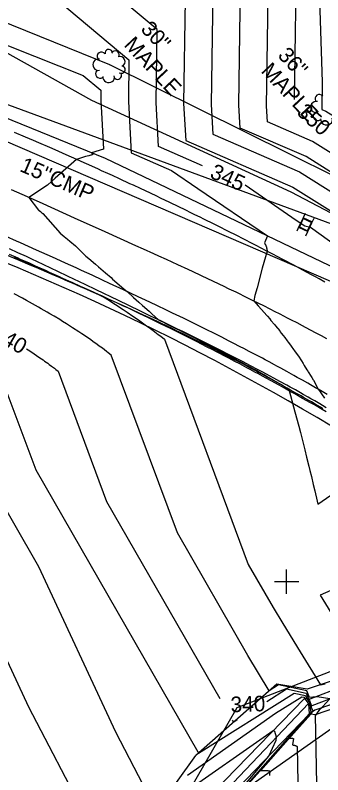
# Model space of a CAD drawing. Extents: x 487096 to 489566, y 221939 to 224454.
# Drawn here: x 488276.8 to 488339.9, y 223512.7 to 223668.7 of the extents above; entities that cross this region are included whole.
import ezdxf

# ---------------------------------------------------------------- set-up
doc = ezdxf.new("R2010")
doc.units = 0
for name, color, linetype in [('SV_BKLN_BKLN', 7, 'Continuous'), ('SV_BKLN_EARTH_TOP', 7, 'Continuous'), ('SV_GDRL_GR', 7, 'Continuous'), ('SV_PIPE_CM_15', 7, 'Continuous'), ('SV_PIPE_CM_TX', 7, 'Continuous'), ('SV_ROAD_BITRD', 7, 'Continuous'), ('SV_ROWL_HWYLOC', 7, 'Continuous'), ('SV_SIGN_SIGN', 7, 'Continuous'), ('SV_SURF_INDEX_CONTOUR', 7, 'Continuous'), ('SV_SURF_INTER_CONTOUR', 7, 'Continuous'), ('SV_SURF_SPOT', 7, 'Continuous'), ('SV_TRAF_PVMTL', 7, 'Continuous'), ('SV_TREE_TREELN', 7, 'Continuous'), ('SV_TREE_TREEVEG', 7, 'Continuous'), ('SV_TREE_TREEVEG_TX', 7, 'Continuous'), ('SV_UTOH_OVERHEAD_LINES', 7, 'Continuous'), ('SV_WATR_INWETF', 7, 'Continuous'), ('SV_WATR_STREAM', 7, 'Continuous')]:
    doc.layers.add(name, color=color, linetype=linetype)

msp = doc.modelspace()

# ---------------------------------------------------------------- linework, layer by layer
at = {"layer": 'SV_BKLN_BKLN'}
for points in [[(488339.95, 223587.83), (488339.42, 223588.15), (488338.36, 223588.77), (488337.57, 223589.24), (488337.04, 223589.54), (488335.98, 223590.16), (488335.45, 223590.47), (488334.38, 223591.07), (488333.32, 223591.68), (488332.61, 223592.08), (488331.18, 223592.88), (488329.97, 223593.55), (488329.16, 223593.99), (488328.62, 223594.28), (488327.55, 223594.87), (488326.73, 223595.31), (488326.19, 223595.6), (488325.11, 223596.17), (488323.48, 223597.03), (488322.39, 223597.6), (488321.67, 223597.98), (488320.21, 223598.73), (488319.39, 223599.15), (488317.75, 223599.99), (488316.1, 223600.82), (488315, 223601.36), (488314.27, 223601.73), (488312.8, 223602.45), (488311.14, 223603.26), (488310.04, 223603.8), (488309.3, 223604.15), (488307.82, 223604.86), (488306.71, 223605.39), (488305.97, 223605.74), (488304.48, 223606.43), (488303.74, 223606.78), (488302.26, 223607.47), (488300.77, 223608.16), (488299.78, 223608.61), (488297.79, 223609.52), (488295.94, 223610.35), (488294.7, 223610.9), (488293.88, 223611.27), (488292.23, 223612), (488291, 223612.55), (488290.17, 223612.91), (488288.52, 223613.63), (488287.69, 223613.99), (488286.04, 223614.7), (488284.39, 223615.42), (488283.28, 223615.89), (488281.07, 223616.83), (488279.83, 223617.36), (488277.34, 223618.4), (488274.85, 223619.44)], [(488394.74, 223534.86), (488364.7, 223537.11), (488337.65, 223526.86), (488337, 223527.31)], [(488337, 223527.31), (488308.63, 223497.45)]]:
    msp.add_lwpolyline(points, dxfattribs=at)
at = {"layer": 'SV_BKLN_EARTH_TOP'}
for points in [[(488393.96, 223536.98), (488391.41, 223542.53), (488364.31, 223539.49), (488336.74, 223530.25), (488330.51, 223531.3), (488313.83, 223516.63)], [(488395.58, 223534.31), (488365.44, 223534.31), (488338.38, 223524.96), (488337.45, 223525.1)], [(488337.45, 223525.1), (488314.81, 223499.82)], [(488301.95, 223500.02), (488313.83, 223516.63)]]:
    msp.add_lwpolyline(points, dxfattribs=at)
at = {"layer": 'SV_GDRL_GR'}
msp.add_lwpolyline([(488340.6, 223587.23), (488339.8, 223587.69), (488338.2, 223588.61), (488337.39, 223589.07), (488335.79, 223589.97), (488334.18, 223590.88), (488333.11, 223591.48), (488332.39, 223591.87), (488331.44, 223592.4), (488330.96, 223592.67), (488329.34, 223593.55), (488328.27, 223594.14), (488327.55, 223594.53), (488326.59, 223595.05), (488326.11, 223595.31), (488325.03, 223595.89), (488324.31, 223596.27), (488323.34, 223596.79), (488322.86, 223597.04), (488321.9, 223597.55), (488320.61, 223598.23), (488319.97, 223598.56), (488318.52, 223599.32), (488317.07, 223600.07), (488316.34, 223600.44), (488314.89, 223601.18), (488314.16, 223601.55), (488313.07, 223602.11), (488311.43, 223602.93), (488309.78, 223603.75), (488308.96, 223604.16), (488307.5, 223604.88), (488306.76, 223605.24), (488305.66, 223605.77), (488304.01, 223606.57), (488302.35, 223607.36), (488301.53, 223607.76), (488299.87, 223608.54), (488299.03, 223608.93), (488297.79, 223609.52), (488295.95, 223610.36), (488294.73, 223610.93), (488293.91, 223611.3), (488292.27, 223612.04), (488291.04, 223612.6), (488290.22, 223612.97), (488288.58, 223613.7), (488287.76, 223614.06), (488286.11, 223614.79), (488284.47, 223615.51), (488283.37, 223615.98), (488282.63, 223616.3), (488281.16, 223616.93), (488279.92, 223617.46), (488279.09, 223617.82), (488277.44, 223618.52), (488276.61, 223618.87)], dxfattribs=at)
at = {"layer": 'SV_PIPE_CM_15'}
msp.add_lwpolyline([(488383.93, 223595.7), (488200.04, 223675.13)], dxfattribs=at)
at = {"layer": 'SV_ROAD_BITRD'}
for points in [[(488436.8, 223529.84), (488436.16, 223531.3), (488435.52, 223532.76), (488434.87, 223534.21), (488434.21, 223535.66), (488433.55, 223537.11), (488433.5, 223537.21), (488438.04, 223566.2), (488412.1, 223588.33), (488389.51, 223592.95), (488385.2, 223591.02), (488344.38, 223615.78), (488295.35, 223639.2), (488243.64, 223660.28)], [(488340.64, 223588.06), (488339.85, 223588.52), (488339.32, 223588.83), (488338.27, 223589.44), (488337.48, 223589.89), (488336.95, 223590.19), (488335.9, 223590.79), (488335.37, 223591.09), (488334.31, 223591.69), (488333.24, 223592.28), (488332.53, 223592.67), (488331.11, 223593.45), (488329.9, 223594.1), (488329.1, 223594.53), (488327.49, 223595.39), (488326.68, 223595.82), (488325.06, 223596.66), (488323.44, 223597.51), (488322.35, 223598.07), (488321.63, 223598.44), (488320.18, 223599.17), (488319.37, 223599.59), (488317.73, 223600.41), (488316.1, 223601.23), (488315, 223601.77), (488312.82, 223602.86), (488311.17, 223603.67), (488310.08, 223604.2), (488307.88, 223605.27), (488306.78, 223605.81), (488304.59, 223606.87), (488302.39, 223607.93), (488297.99, 223610.05), (488293.41, 223612.26), (488291.12, 223613.36), (488287.68, 223615.01), (488285.39, 223616.1), (488284.24, 223616.65), (488282.52, 223617.46), (488280.22, 223618.55), (488279.07, 223619.09), (488277.35, 223619.89), (488275.62, 223620.69)]]:
    msp.add_lwpolyline(points, dxfattribs=at)
at = {"layer": 'SV_ROWL_HWYLOC'}
msp.add_lwpolyline([(487756.92, 223854.03), (487819.74, 223823.93), (487982.51, 223759.36), (488009.69, 223754.74), (488041.14, 223750.63), (488071.96, 223735.45), (488100.92, 223722.74), (488124.66, 223715.6), (488155.68, 223709.25), (488178.9, 223706.07), (488296.16, 223658.56), (488379.4, 223617.17), (488410.15, 223595.68), (488443.8, 223549.21), (488472.24, 223469.86), (488477.06, 223418.16), (488475.62, 223352.08), (488474.08, 223317.48), (488463.17, 223231.25), (488461.58, 223189.46)], dxfattribs=at)
msp.add_arc((488082.83, 223151.77), 504.05, 56.3623, 68.8615, dxfattribs=at)
at = {"layer": 'SV_SIGN_SIGN'}
for p, q in [((488336.27, 223627.93), (488335.86, 223627.05)), ((488337.7, 223626.04), (488338.13, 223626.98)), ((488335.01, 223625.26), (488334.57, 223624.34)), ((488336.46, 223623.37), (488336.87, 223624.25))]:
    msp.add_line(p, q, dxfattribs=at)
for points in [[(488335.87, 223627.06), (488335.02, 223625.25), (488336.8, 223624.41), (488337.65, 223626.22)], [(488336.85, 223624.24), (488337.7, 223626.05), (488335.91, 223626.88), (488335.07, 223625.06)]]:
    msp.add_lwpolyline(points, close=True, dxfattribs=at)
at = {"layer": 'SV_SURF_INDEX_CONTOUR'}
for points in [[(488315.25, 223637.73), (488306.19, 223641.67), (488305.69, 223650.74), (488305.9, 223665.72), (488280.6, 223686.87), (488279.19, 223687.43), (488278.94, 223688.82), (488279.46, 223690.16), (488279.91, 223705.25)], [(488334.21, 223693.47), (488334.54, 223683.57), (488334.08, 223651.34)], [(488346.42, 223618.58), (488337.38, 223625.05), (488336.21, 223625.31), (488334.48, 223626.49), (488323.99, 223633.76)], [(488279.07, 223600.15), (488279.76, 223599.71), (488280.71, 223599.09), (488281.17, 223598.78), (488281.84, 223598.32), (488282.51, 223597.86), (488282.83, 223597.63), (488283.47, 223597.17), (488283.78, 223596.94), (488284.25, 223596.6), (488284.85, 223596.15), (488285.15, 223595.92), (488285.58, 223595.58), (488295.54, 223568.82), (488318.79, 223528.32)], [(488328.41, 223527.75), (488332.45, 223530.29), (488336.48, 223529.45), (488336.98, 223528.22), (488337.21, 223527.93), (488337.51, 223526.96), (488337.55, 223526.47), (488337.97, 223525.72), (488337.39, 223525.12), (488333.04, 223520.17), (488333.06, 223520.17), (488333.15, 223520.17), (488333.23, 223520.17), (488333.32, 223520.17), (488333.4, 223520.17), (488333.47, 223520.17), (488333.55, 223520.17), (488333.62, 223520.16), (488333.69, 223520.16), (488333.75, 223520.15), (488333.82, 223520.15), (488333.88, 223520.14), (488333.72, 223518.8), (488333.79, 223518.79), (488333.86, 223518.78), (488333.93, 223518.77), (488333.99, 223518.75), (488334.06, 223518.74), (488334.11, 223518.72), (488334.17, 223518.71), (488334.23, 223518.7), (488334.28, 223518.68), (488334.33, 223518.67), (488334.38, 223518.65), (488334.42, 223518.64), (488334.46, 223518.62), (488334.5, 223518.6), (488334.53, 223518.57), (488334.56, 223518.55), (488334.59, 223518.53), (488334.62, 223518.51), (488334.65, 223518.48), (488335.11, 223492.49)], [(488322.34, 223523.94), (488321.65, 223523.5), (488321.41, 223523.91)]]:
    msp.add_lwpolyline(points, dxfattribs=at)
at = {"layer": 'SV_SURF_INTER_CONTOUR'}
for points in [[(488344.4, 223638.61), (488337.84, 223642.72), (488328.56, 223646.76), (488328.39, 223649.96), (488328.96, 223690.61)], [(488338.62, 223690.85), (488339.81, 223654.94), (488339.74, 223649.58), (488339.75, 223649.3), (488340.55, 223648.95), (488341.11, 223648.6), (488357.67, 223638.69), (488363.82, 223635.84), (488384.77, 223627.51), (488386.19, 223626.24), (488404.97, 223613.69), (488414.47, 223607.86), (488430.46, 223603.61), (488430.99, 223603.65), (488432.06, 223604.18), (488443, 223609.09)], [(488346.04, 223633.62), (488336.49, 223639.61), (488322.97, 223645.48), (488322.71, 223650.16), (488323.2, 223684.39)], [(488317.43, 223678.16), (488317.04, 223650.35), (488317.37, 223644.21), (488335.13, 223636.49), (488347.68, 223628.62)], [(488285.67, 223671.59), (488300.14, 223659.5), (488300.02, 223650.93), (488300.59, 223640.39), (488308.89, 223636.78), (488314.27, 223633.05), (488328.54, 223623.34), (488327.95, 223621.89), (488328.01, 223621.78), (488328.11, 223621.6), (488328.14, 223621.54), (488328.2, 223621.4), (488328.25, 223621.29), (488328.28, 223621.21), (488328.34, 223621.05), (488328.38, 223620.91), (488328.44, 223620.69), (488328.53, 223620.22), (488328.53, 223620.17), (488327.47, 223616.69), (488326.45, 223612.7), (488326, 223611.13), (488325.74, 223609.98), (488326.66, 223608.99), (488326.72, 223608.92), (488327.3, 223608.28), (488327.35, 223608.22), (488328.42, 223607.02), (488328.54, 223606.86), (488329.04, 223606.29), (488329.29, 223605.97), (488330, 223605.14), (488330.21, 223604.86), (488331.07, 223603.83), (488331.19, 223603.66), (488331.4, 223603.37), (488331.79, 223602.89), (488332.1, 223602.45), (488332.64, 223601.78), (488332.81, 223601.53), (488333.28, 223600.93), (488333.56, 223600.52), (488333.77, 223600.24), (488334.24, 223599.53), (488334.92, 223598.61), (488335.54, 223597.65), (488335.88, 223597.1), (488336.13, 223596.75), (488336.68, 223595.84), (488336.87, 223595.57), (488336.95, 223595.44), (488337.53, 223594.45), (488337.65, 223594.28), (488337.95, 223593.75), (488337.99, 223593.68), (488338.63, 223592.54), (488338.65, 223592.5), (488338.99, 223591.88), (488338.99, 223591.88), (488339.03, 223591.79), (488339.54, 223591.08), (488339.67, 223590.88), (488340.26, 223590.03)], [(488311.67, 223671.94), (488311.36, 223650.54), (488311.78, 223642.94), (488333.78, 223633.37), (488349.32, 223623.63)], [(488265.33, 223666.37), (488290.74, 223656.31), (488294.37, 223653.27), (488294.34, 223651.12), (488294.89, 223641.12), (488292.47, 223640.37), (488292.73, 223640.05), (488292.73, 223640.04), (488292.71, 223640.04), (488292.7, 223640.03), (488292.67, 223640.02), (488292.63, 223640), (488292.59, 223639.99), (488292.5, 223639.97), (488292.4, 223639.94), (488292.31, 223639.92), (488292.07, 223639.85), (488291.88, 223639.8), (488291.22, 223639.61), (488289.37, 223639.05), (488284.99, 223635.2), (488283.38, 223633.78), (488279.59, 223631.2), (488281.6, 223628.62), (488281.72, 223628.53), (488281.97, 223628.32), (488282.25, 223628.09), (488282.45, 223627.92), (488286, 223623.89), (488286.83, 223623.24), (488287.52, 223622.68), (488288.02, 223622.26), (488289.14, 223621.32), (488291.26, 223619.2), (488291.88, 223618.69), (488293.25, 223617.56), (488293.88, 223616.96), (488295.35, 223615.72), (488296.45, 223614.79), (488296.78, 223614.48), (488299.1, 223612.47), (488299.18, 223612.41), (488299.75, 223611.9), (488301.09, 223610.66), (488302.15, 223609.74), (488302.94, 223609.02), (488304.26, 223607.85), (488304.83, 223607.33), (488306.21, 223606.08), (488306.77, 223605.8), (488306.78, 223605.8), (488307.83, 223605.28), (488307.88, 223605.26), (488307.94, 223605.22), (488310, 223604.2), (488310.07, 223604.16), (488311.03, 223603.68), (488311.17, 223603.61), (488312.54, 223602.92), (488312.81, 223602.79), (488313.09, 223602.65), (488314.83, 223601.76), (488315, 223601.67), (488315.8, 223601.27), (488316.1, 223601.11), (488317.22, 223600.54), (488317.74, 223600.27), (488318.77, 223599.74), (488319.38, 223599.42), (488319.86, 223599.17), (488320.2, 223598.99), (488320.99, 223598.57), (488321.65, 223598.22), (488322.01, 223598.02), (488322.37, 223597.83), (488322.88, 223597.56), (488323.46, 223597.24), (488324.14, 223596.88), (488325.09, 223596.36), (488325.81, 223595.96), (488326.35, 223595.67), (488326.72, 223595.46), (488326.96, 223595.33), (488327.53, 223595.01), (488327.93, 223594.79), (488328.72, 223594.34), (488329.15, 223594.09), (488329.3, 223594.01), (488329.96, 223593.63), (488330.13, 223593.53), (488331.17, 223592.93), (488331.29, 223592.86), (488332.6, 223592.09), (488332.62, 223592.08), (488332.94, 223591.89), (488333.3, 223590.59), (488334.2, 223587.21), (488334.97, 223584.28), (488335.32, 223582.95), (488335.94, 223580.53), (488336.22, 223579.43), (488336.61, 223577.89), (488337.08, 223576.02), (488337.29, 223575.16), (488337.58, 223573.95), (488337.98, 223572.3), (488338.29, 223570.97), (488338.43, 223570.35), (488338.63, 223569.47), (488338.91, 223568.25), (488348.2, 223574.66)], [(488275.57, 223619.57), (488277.34, 223618.81), (488277.8, 223618.59), (488279.64, 223617.78), (488279.92, 223617.64), (488280.88, 223617.22), (488281.39, 223616.97), (488283.13, 223616.2), (488283.47, 223616.04), (488284.36, 223615.64), (488284.57, 223615.54), (488285.94, 223614.93), (488286.29, 223614.75), (488287.69, 223614.12), (488288.42, 223613.79), (488288.82, 223613.6), (488290.26, 223612.95), (488291.01, 223612.61), (488292.17, 223612.07), (488292.29, 223612.01), (488293.87, 223611.29), (488294.7, 223610.91), (488294.92, 223610.81), (488295.79, 223610.26), (488297.34, 223609.27), (488298.97, 223608.21), (488299.77, 223607.68), (488300.94, 223606.88), (488302.08, 223606.08), (488302.65, 223605.69), (488303.75, 223604.89), (488304.29, 223604.5), (488305.1, 223603.9), (488306.14, 223603.12), (488306.65, 223602.72), (488307.41, 223602.14), (488324.62, 223555.86), (488329.71, 223547), (488331.69, 223543.71), (488335.28, 223537.89), (488339.42, 223531.15), (488340.42, 223531.36)], [(488339.03, 223493), (488338.45, 223524.92), (488338.53, 223525.01), (488339.45, 223526.3), (488339.69, 223526.42), (488339.84, 223526.6), (488341.37, 223528.27), (488338.76, 223528.65), (488338.56, 223528.66), (488337.2, 223528.51), (488336.63, 223529.92), (488330.86, 223531.12), (488328.91, 223529.89), (488324.55, 223537.13), (488310.08, 223562.34), (488296.5, 223598.86), (488295.9, 223599.32), (488295.5, 223599.63), (488294.67, 223600.25), (488294.04, 223600.72), (488293.61, 223601.03), (488292.74, 223601.66), (488292.3, 223601.97), (488291.39, 223602.6), (488290.47, 223603.23), (488289.84, 223603.65), (488288.55, 223604.49), (488287.33, 223605.27), (488286.5, 223605.79), (488285.93, 223606.14), (488284.79, 223606.83), (488283.92, 223607.35), (488283.33, 223607.69), (488282.14, 223608.38), (488281.54, 223608.72), (488280.32, 223609.41), (488279.08, 223610.09), (488278.25, 223610.55), (488276.56, 223611.46)], [(488274.67, 223592.3), (488281, 223575.29), (488314.24, 223517.39), (488314.4, 223517.12), (488334.03, 223529.46), (488336.34, 223528.98), (488336.62, 223528.28), (488337.12, 223527.66), (488337.29, 223527.11), (488337.38, 223525.83), (488337.6, 223525.45), (488337.3, 223525.15), (488327.12, 223513.56), (488327.16, 223513.56), (488327.37, 223513.56), (488327.57, 223513.57), (488327.76, 223513.56), (488327.95, 223513.56), (488328.13, 223513.55), (488328.3, 223513.55), (488328.47, 223513.54), (488328.63, 223513.52), (488328.79, 223513.51), (488328.94, 223513.5), (488329.08, 223513.48), (488328.96, 223512.52)], [(488291.29, 223504.08), (488279.6, 223526.57), (488253.66, 223582.35)], [(488303.02, 223510.61), (488297.41, 223521.4), (488281.61, 223555.37), (488266.46, 223581.77)], [(488354.96, 223556.41), (488339.36, 223549.58), (488348.75, 223534.28)], [(488321.2, 223506.95), (488337.22, 223525.18), (488337.22, 223525.18), (488337.22, 223525.19), (488337.06, 223527.27), (488337.02, 223527.39), (488336.26, 223528.34), (488336.19, 223528.51), (488335.61, 223528.63), (488330.24, 223525.26), (488312.17, 223512.55)], [(488316.48, 223501.71), (488328.85, 223516.5), (488330.35, 223519.81), (488330.41, 223520.38), (488330.08, 223521.56), (488329.71, 223521.72), (488310.37, 223508.12)]]:
    msp.add_lwpolyline(points, dxfattribs=at)
at = {"layer": 'SV_SURF_SPOT'}
for p, q in [((488332.5, 223549.85), (488332.5, 223554.85)), ((488330, 223552.35), (488335.01, 223552.35)), ((488332.5, 223552.35), (488332.5, 223552.35))]:
    msp.add_line(p, q, dxfattribs=at)
at = {"layer": 'SV_TRAF_PVMTL'}
for points in [[(488340.36, 223613.85), (488339.18, 223614.49), (488338.4, 223614.91), (488337.36, 223615.48), (488336.84, 223615.76), (488335.66, 223616.4), (488334.88, 223616.82), (488333.83, 223617.38), (488333.31, 223617.66), (488332.52, 223618.07), (488331.48, 223618.63), (488330.95, 223618.9), (488329.38, 223619.73), (488328.33, 223620.28), (488326.23, 223621.37), (488325.04, 223621.98), (488324.25, 223622.39), (488323.2, 223622.93), (488322.67, 223623.2), (488321.88, 223623.6), (488320.82, 223624.13), (488320.3, 223624.4), (488318.71, 223625.2), (488317.65, 223625.73), (488315.53, 223626.78), (488314.74, 223627.17), (488313.68, 223627.69), (488313.14, 223627.95), (488311.55, 223628.73), (488310.49, 223629.25), (488308.36, 223630.27), (488306.76, 223631.04), (488305.69, 223631.55), (488303.55, 223632.56), (488302.48, 223633.06), (488301.05, 223633.73), (488300.34, 223634.06), (488298.19, 223635.06), (488296.76, 223635.71), (488295.81, 223636.15), (488294.53, 223636.73), (488293.89, 223637.02), (488291.92, 223637.91), (488290.94, 223638.35), (488289.46, 223639.01), (488287.24, 223640), (488285.01, 223640.98), (488283.89, 223641.46), (488281.66, 223642.43), (488280.55, 223642.91), (488278.87, 223643.63), (488276.63, 223644.58)], [(488340.73, 223602.19), (488339.64, 223602.78), (488338.54, 223603.38), (488336.35, 223604.55), (488335.78, 223604.85), (488334.63, 223605.46), (488333.48, 223606.06), (488332.71, 223606.46), (488331.18, 223607.25), (488330.02, 223607.84), (488329.25, 223608.23), (488327.71, 223609.01), (488326.93, 223609.39), (488325.38, 223610.16), (488323.83, 223610.92), (488322.8, 223611.43), (488322.11, 223611.76), (488320.73, 223612.43), (488319.56, 223612.99), (488318.78, 223613.36), (488317.22, 223614.1), (488316.44, 223614.47), (488314.88, 223615.21), (488313.31, 223615.94), (488312.27, 223616.43), (488310.18, 223617.39), (488307.83, 223618.47), (488306.26, 223619.19), (488305.21, 223619.67), (488303.11, 223620.62), (488301.54, 223621.33), (488298.39, 223622.75), (488295.24, 223624.17), (488288.94, 223626.99), (488282.5, 223629.89), (488279.28, 223631.34), (488276.05, 223632.78)], [(488340.81, 223590.74), (488339.76, 223591.37), (488338.96, 223591.83), (488338.43, 223592.14), (488337.37, 223592.76), (488336.83, 223593.07), (488335.76, 223593.68), (488334.69, 223594.28), (488333.98, 223594.68), (488332.54, 223595.48), (488331.33, 223596.15), (488330.52, 223596.59), (488329.98, 223596.89), (488328.89, 223597.47), (488328.08, 223597.91), (488327.54, 223598.2), (488326.45, 223598.77), (488324.81, 223599.63), (488323.71, 223600.2), (488322.98, 223600.58), (488321.52, 223601.33), (488320.7, 223601.75), (488319.05, 223602.58), (488317.39, 223603.41), (488316.29, 223603.96), (488315.55, 223604.33), (488314.07, 223605.06), (488312.41, 223605.87), (488311.3, 223606.41), (488309.07, 223607.48), (488307.96, 223608.02), (488305.73, 223609.08), (488303.5, 223610.14), (488302.01, 223610.84), (488299.04, 223612.24), (488296.15, 223613.58), (488294.71, 223614.25), (488292.55, 223615.25), (488290.38, 223616.25), (488289.3, 223616.75), (488287.13, 223617.74), (488286.05, 223618.23), (488284.42, 223618.97), (488282.25, 223619.94), (488281.16, 223620.43), (488279.53, 223621.16), (488277.9, 223621.88), (488277.08, 223622.24), (488274.9, 223623.19)]]:
    msp.add_lwpolyline(points, dxfattribs=at)
at = {"layer": 'SV_TREE_TREELN'}
msp.add_lwpolyline([(488222.16, 223685.58), (488260.7, 223668.96), (488292.44, 223651.19), (488333.36, 223632.41), (488374.4, 223610.79), (488410.05, 223595.83)], dxfattribs=at)
at = {"layer": 'SV_TREE_TREEVEG'}
msp.add_line((488296.1, 223658.25), (488296.1, 223658.25), dxfattribs=at)
for centre, radius, start, end in [((488295.99, 223660.9), 0.75, 23.2911, 192.3579), ((488294.49, 223660.22), 0.874, 35.9933, 211.459), ((488297.31, 223660.49), 0.85, 345.5308, 152.7093), ((488298.27, 223659.13), 1.06, 294.1859, 111.1082), ((488293.9, 223658.5), 1.17, 79.3292, 279.9889), ((488294.19, 223656.65), 0.922, 137.0157, 304.5501), ((488339.19, 223651.51), 0.874, 35.9933, 211.459), ((488338.61, 223649.79), 1.17, 79.3292, 279.9889), ((488338.89, 223647.94), 0.922, 137.0157, 304.5501)]:
    msp.add_arc(centre, radius, start, end, dxfattribs=at)
for centre, major_axis, ratio, start_param, end_param in [((488298.56, 223657.49), (0.822, -0.013), 0.901056, 4.216583, 7.444153), ((488295.97, 223655.92), (-1.2, 0.16), 0.902156, 0, 3.5401), ((488297.82, 223656.28), (0.08, -0.798), 0.999752, 5.391582, 8.241319), ((488340.68, 223647.21), (-1.2, 0.16), 0.902156, 0, 3.5401)]:
    msp.add_ellipse(centre, major_axis=major_axis, ratio=ratio, start_param=start_param, end_param=end_param, dxfattribs=at)
at = {"layer": 'SV_UTOH_OVERHEAD_LINES'}
msp.add_lwpolyline([(488477.01, 222631.44), (488424.13, 222778.25), (488391.68, 223012.96), (488449.87, 223205.72), (488470, 223438.33), (488349.56, 223622.89), (488159.18, 223693.12), (487993.17, 223755.78), (487804.2, 223830.22), (487742.26, 223860.21)], dxfattribs=at)
at = {"layer": 'SV_WATR_INWETF'}
for points in [[(488392.95, 223538.47), (488377.59, 223540.37), (488348.65, 223536.59), (488322.28, 223526.42), (488300.73, 223488.93), (488278.08, 223417.7)], [(488318.07, 223481.95), (488317.38, 223505.04), (488351.68, 223529.23), (488396.35, 223531.52)]]:
    msp.add_lwpolyline(points, dxfattribs=at)
at = {"layer": 'SV_WATR_STREAM'}
for points in [[(488394.53, 223535.42), (488391.87, 223536.78), (488364.35, 223538.58), (488337.29, 223528.17), (488336.14, 223528.36)], [(488395.6, 223534.31), (488365.27, 223535.12), (488338.28, 223525.94), (488337.22, 223525.18)], [(488336.14, 223528.36), (488305.9, 223497.17)], [(488337.22, 223525.18), (488311.15, 223498.15)]]:
    msp.add_lwpolyline(points, dxfattribs=at)

# ---------------------------------------------------------------- texts
at = {"layer": 'SV_PIPE_CM_TX'}
msp.add_text("15''CMP", height=3.2, rotation=336.6384, dxfattribs=at).set_placement((488277.52, 223636.7))
at = {"layer": 'SV_SURF_INDEX_CONTOUR'}
for s, rotation, p in [('350', 317.792, (488334.39, 223648.48)), ('345', 335.6027, (488316.54, 223635.38)), ('340', 330.1148, (488271.81, 223602.47)), ('340', 1.988, (488321.04, 223525.49))]:
    msp.add_text(s, height=3.2, rotation=rotation, dxfattribs=at).set_placement(p)
at = {"layer": 'SV_TREE_TREEVEG_TX'}
for s, p in [('30"', (488302.38, 223665.65)), ('MAPLE', (488298.94, 223662.44)), ('36"', (488330.51, 223660.27)), ('MAPLE', (488327.07, 223657.07))]:
    msp.add_text(s, height=3.2, rotation=313.0386, dxfattribs=at).set_placement(p)

doc.saveas('drawing.dxf')
